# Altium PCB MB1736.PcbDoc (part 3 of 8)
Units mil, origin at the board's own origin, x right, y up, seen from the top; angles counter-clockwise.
Board outline 5905.51 x 3779.53 mil, 6 copper layers (Top Layer, L2_GND, L3_SIG, L4_VCC, L5_GND, Bottom Layer), stack 117.811 mil thick; 481 components, 387 nets, 1904 pads, 1200 vias.
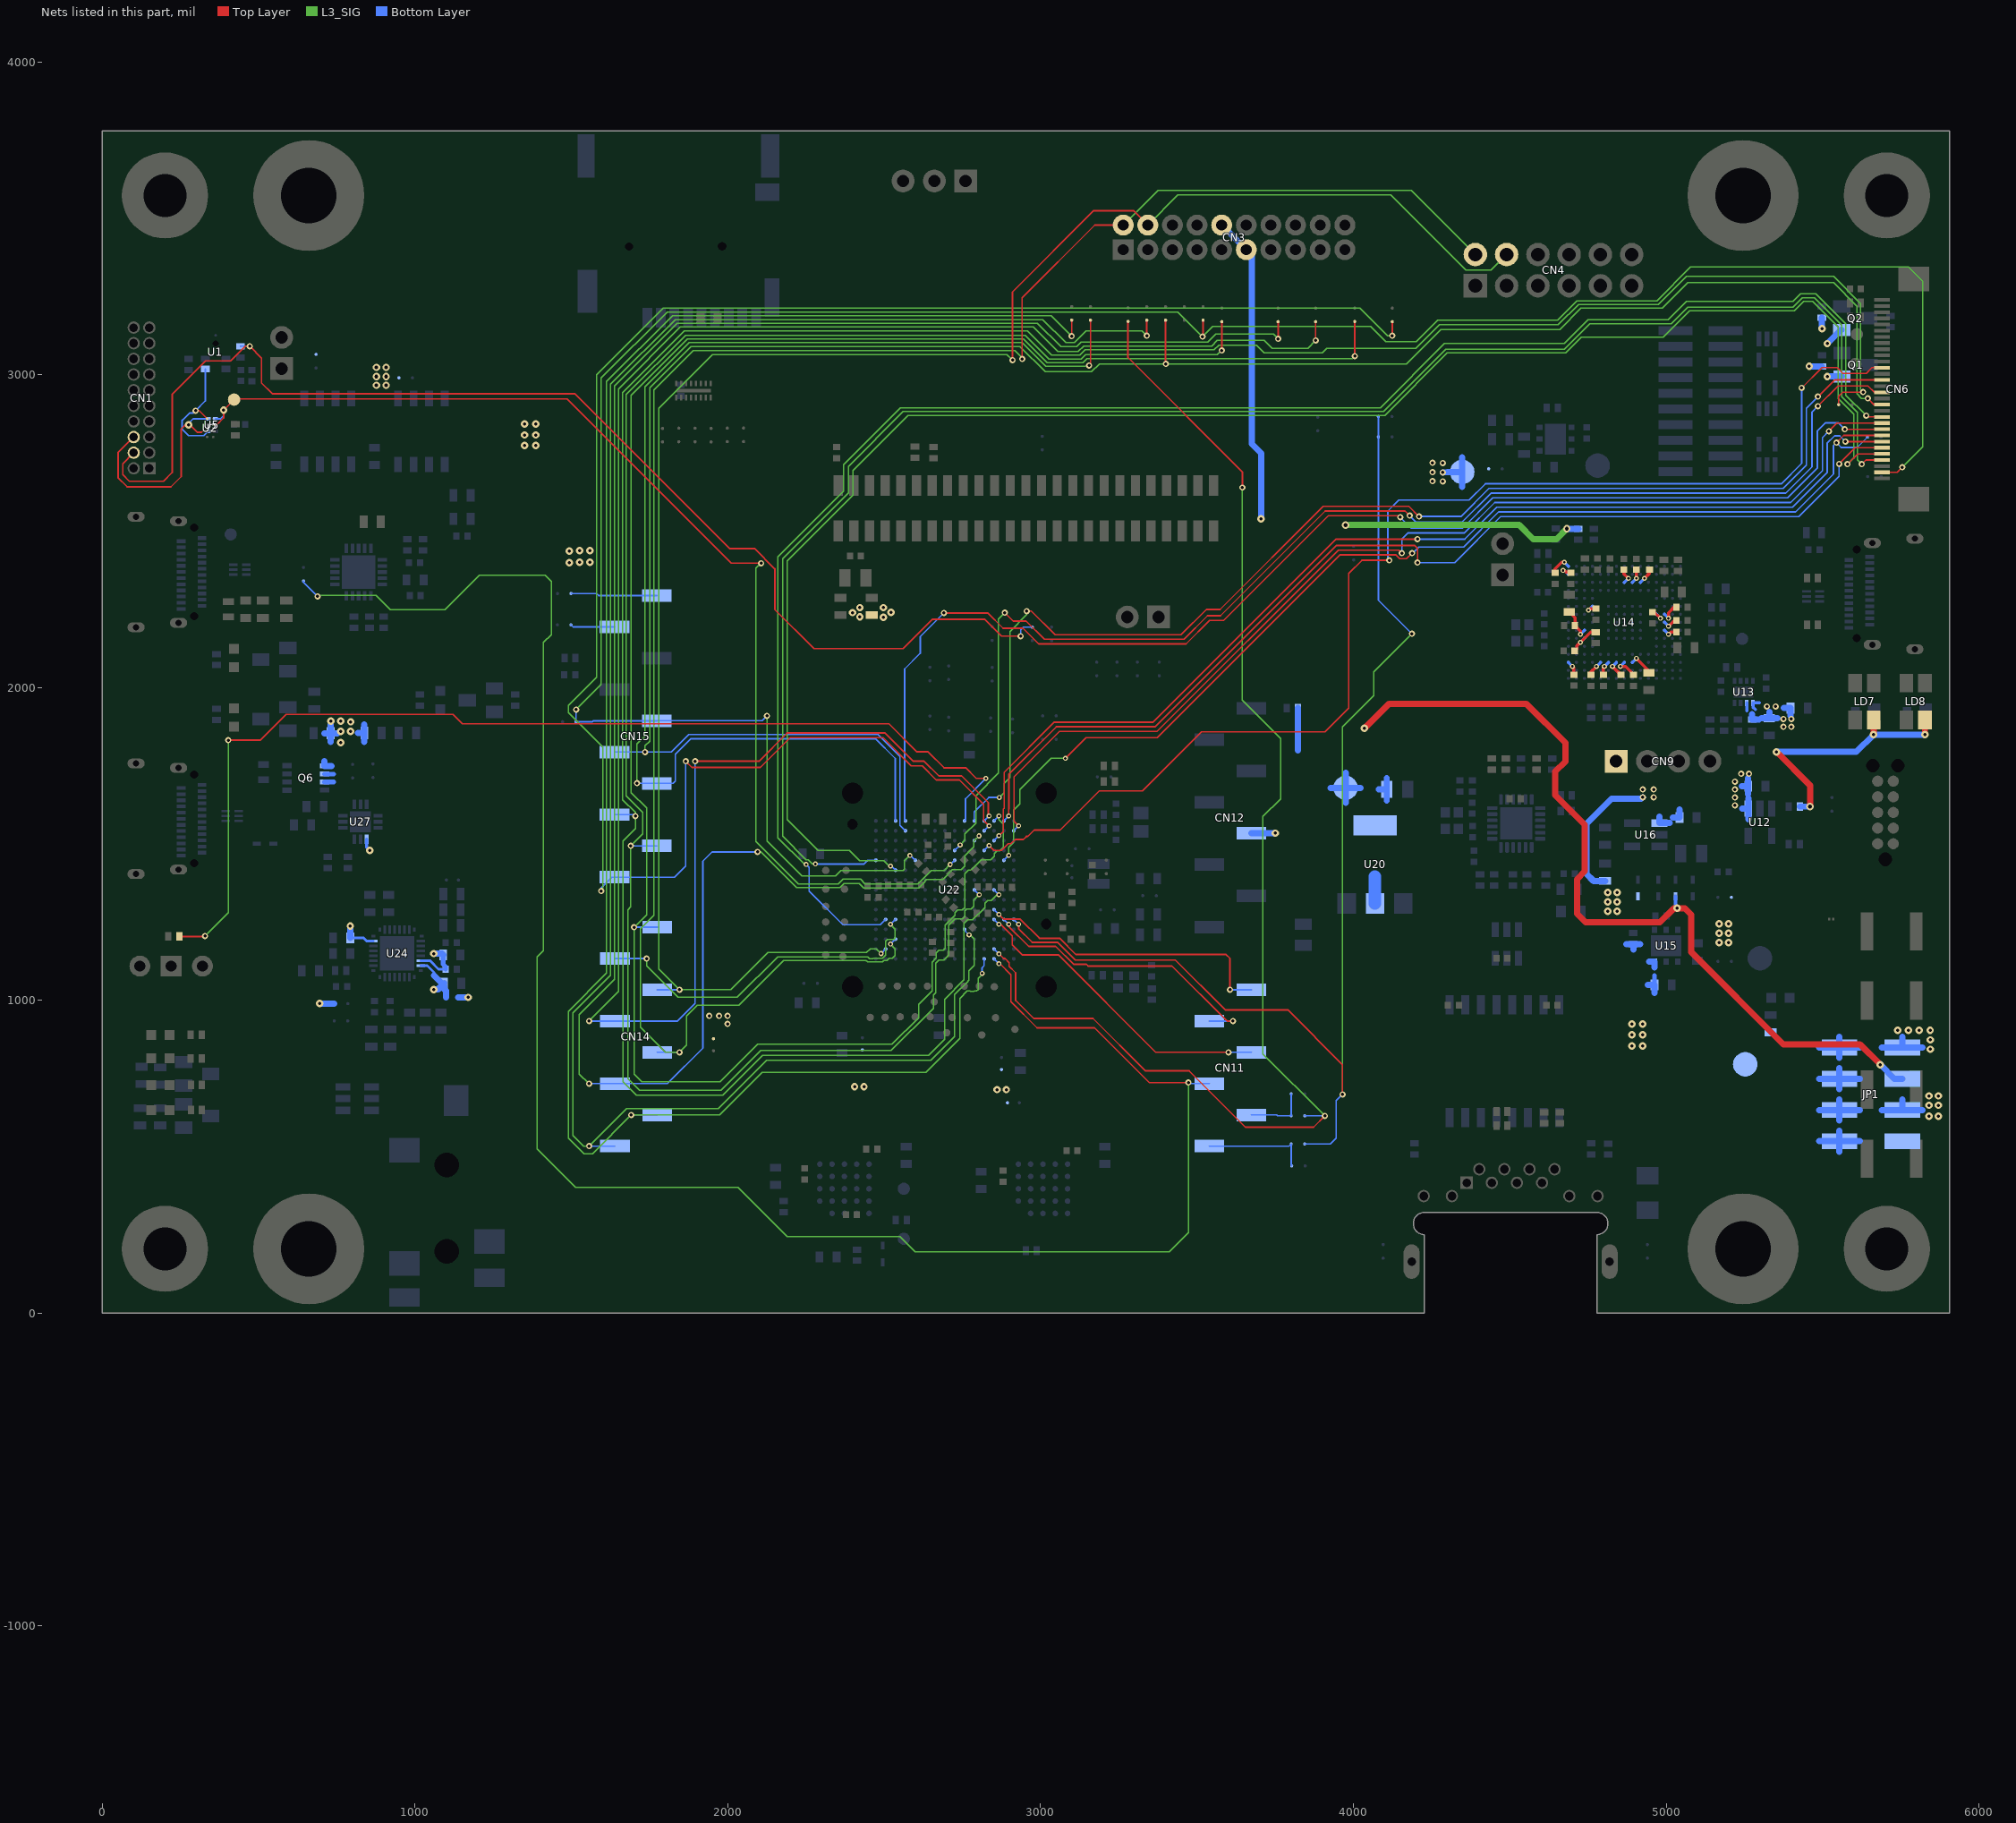
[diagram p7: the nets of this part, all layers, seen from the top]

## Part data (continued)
TP12 TP13 TP14 TP15 TP16 TP17 TP18 TP19 TP20 TP21 TP22 TP23 TP24 TP25 TP26 TP27 TP28 TP29 TP30 TP31 TP32 TP33 TP34 TP35 TP36 TP37 TP38 TP39 TP40 TP41 TP42: library part MCD-00631, "Test Point 0.6mm", Manufacturer=N/A
U1: library part MCD-02122, "MEMS sensors , omnidirectionnal digital microphone", Manufacturer=STMICROELECTRONICS, Manufacturer_HQ_COO=EU, Manufacturer_Part_Number=MP23DB01HPTR, Package="RHLGA 5"
U2: library part MCD-00668, "Low voltage 0.5 ohm single SPDT switch with break-before-make feature and 15 kV contact ESD protection", Manufacturer=STMICROELECTRONICS, Manufacturer_HQ_COO=EU, Manufacturer_Part_Number=STG4160BJR, Package="Flip Chip 8"
U3: library part MCD-00249, "ESD protection for SD card 2.0", Manufacturer=STMICROELECTRONICS, Manufacturer_HQ_COO=EU
U4 U10 U11: library part MCD-00136, "Dual Transil array for ESD protection", Manufacturer=STMICROELECTRONICS, Manufacturer_HQ_COO=EU
U5: library part MCD-02386, "Analog Switch, Low-ohmic single-pole double-throw analog switch", Manufacturer=NXP, Manufacturer_Part_Number=NX3L1T3157GMZ, Package=SOT886-6
U6 U7: library part MCD-03501, "Diode, ESD TVS, 5V5, 100nA, 10V, 0201", Manufacturer=STMICROELECTRONICS, Manufacturer_Part_Number=ESDZL5-1F4, Package=0201
U8 U29 U30: library part MCD-03060, "IC, ESD protection and Common Filter High Speed serial Interfaces, 10.7 GHz", Manufacturer=STMICROELECTRONICS, Package=uQFN-6
U9 U31 U32: library part MCD-01207, "High power Transient voltage suppressor:25V/35A EOS and ESD transients protection.", Manufacturer=STMICROELECTRONICS, Manufacturer_HQ_COO=EU, Manufacturer_Part_Number=ESDA25P35-1U1M, Package=QFN1610
U12: library part MCD-00159, "500mA, Enhanced single channel power switches with active high enable pin", Manufacturer=STMICROELECTRONICS, Manufacturer_HQ_COO=EU
U13: library part MCD-02532, "IC, eFuse with Fast Overvoltage Protection 2.7V to 18V 4A 34mOhm 8-Pin WSON", Manufacturer="TEXAS INSTRUMENTS", Package=WSON8
U14: library part MCD-02706, "MCU, Arm Cortex-M7 32-bit MCU, 512KB Flash, 276KB RAM, With Crypto", Manufacturer=STMICROELECTRONICS, Manufacturer_Part_Number=STM32F723IEK6, Package=BGA176
U15: library part MCD-01025, "LDO, 3.3V, 1.3A, Very low quiescent current BiCMOS voltage regulator", Manufacturer=STMICROELECTRONICS, Manufacturer_HQ_COO=EU, Package=DFN6-3x3
U16: library part MCD-02514, "LDO, 3.3V, 300mA, High input voltage: 2.5V to 28V, SOT23-5L", Manufacturer=STMICROELECTRONICS, Package=SOT23-5L
U17: library part MCD-00581, "LDO Linear Voltage Regulator IC Positive Adjustable 1 Output Adjustable 1.3A 6-DFN (3x3)", Manufacturer=STMICROELECTRONICS, Manufacturer_HQ_COO=EU, Package="DFN6 (3x3)"
U18: library part MCD-00719, "10/100M RMII Ethernet transceiver", Manufacturer=MICROCHIP
U19: library part MCD-00250, "Very low capacitance ESD protection , 4 lines", Manufacturer=STMICROELECTRONICS, Manufacturer_HQ_COO=EU
U20: library part MCD-00088, "IC REG LDO 5V 0.8A SOT223", Manufacturer=STMICROELECTRONICS, Manufacturer_HQ_COO=EU, Package=SOT-223
U21: library part MCD-02129, "Memory,Hexa-SPI-PSRAM,256Mb,x8x16,200MHz,1.8V,DDR,BGA24, PASR LVCMOS", Manufacturer="AP MEMORY TECHNOLOGY CORP.", Package=BGA24
U22: library part MCD-02603, "MCU, ARM Cortex M7 32-bit, 64KB Flash, 620KB RAM, No Crypto", Manufacturer=STMICROELECTRONICS, Package=TFBGA-225
U23: library part MCD-02601, "Memory, Octo-SPI-NOR, 1Gb,x1/x8, Read-While-Write, 133/200MHz, 1.8V, DTR, BGA24", Manufacturer=MACRONIX, Package=BGA24
U24: library part MCD-03825, "Audio Codec, Ultra Low-Power Codec for Portable Audio Applications", Manufacturer="CIRRUS LOGIC"
U26: library part MCD-02130, "USB Type-C Port Protection for USB DRP Power Delivery, PPS compliant", Manufacturer=STMICROELECTRONICS, Manufacturer_HQ_COO=EU, Package=QFN-20L
U27: library part MCD-01809, "USB Type-C Port Protection for USB Power Delivery, PPS compliant", Manufacturer=STMICROELECTRONICS, Manufacturer_HQ_COO=EU, Package=QFN-12L
U28: library part MCD-00247, "Quad Bidir ESD protection", Manufacturer=STMICROELECTRONICS, Manufacturer_HQ_COO=EU
U33: library part MCD-00718, "Discrete Magnetic Transformer Module, 16 pins, SMT, 100 Base-TX", Manufacturer="DONGGUAN KEYOUDA ELECTRONIC TECHNOLOGY"
X1: library part MCD-01036, "Crystal, 24MHz, 6pF, +/-20ppm, 80R, 2x1.6mm", Manufacturer=NDK, Manufacturer_Part_Number=NX2016SA-24MHZ-EXS00A-CS10820, Package=2x1.6mm
X2: library part MCD-01479, "Crystal, 32.768kHz, 6pF, +/-20ppm, 80K, 2.05x1.2mm", Manufacturer=NDK, Manufacturer_Part_Number=NX2012SA-32.768KHZ-EXS00A-MU00527, Package=2.05x1.2mm
X3: library part MCD-01627, "Oscillator, SPXO, 24MHz, +/-50ppm, square wave, 3V3, 2x1.6mm", Manufacturer=NDK, Manufacturer_Part_Number=NZ2016SH-24MHZ-END4869F, Package=2x1.6mm
X4: library part MCD-01364, "Crystal, 25MHz, 6pF, +/-20ppm, 80R, 2x1.6mm", Manufacturer=NDK, Manufacturer_Part_Number=NX2016SA-25MHZ-EXS00A-CS11321, Package=2x1.6mm

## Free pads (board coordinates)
  round 20 on Mech16: 1(1689.63,-1444.91) 1(3612.76,-1444.91)

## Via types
v1: diameter 20, hole 10, Top Layer to Bottom Layer, tented both sides, 518 vias
v2: diameter 16, hole 8, Top Layer to Bottom Layer, tented both sides, 311 vias
v3: diameter 24, hole 10, Top Layer to Bottom Layer, tented both sides, 301 vias
v4: diameter 24, hole 12, Top Layer to Bottom Layer, tented both sides, 61 vias
v5: diameter 23.62, hole 11.81, Top Layer to Bottom Layer, 9 vias

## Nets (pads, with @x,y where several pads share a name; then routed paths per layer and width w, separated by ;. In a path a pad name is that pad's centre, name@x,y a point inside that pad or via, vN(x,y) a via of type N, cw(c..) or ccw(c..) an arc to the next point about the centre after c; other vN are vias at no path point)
1V8: Q1.1 Q2.1 R64.2 R65.2 SB23.2 SB38.1 SB48.1 SB60.1 SB66.1 SB67.1 TP7.1 | length 376.8
  Bottom Layer w20: SB60.1@1137.72,1010 v3(1170.16,1010) ; v1(4285.9,2688.19) 4300.44,2689.77 TP7.1@4347.83,2689.77 ; 4347.83,2642.39 TP7.1@4347.83,2689.77 ; 4347.83,2737.17 TP7.1@4347.83,2689.77 ; v3(5457.72,3027.27) R64.2@5498,3027.3 ; v3(5497.95,3147.94) R65.2@5497.95,3183.48 ; v3(5515,2994.8) Q1.1@5562.19,2994.81 ; v3(5515,3100) 5558.79,3143.78 Q2.1@5561.37,3143.79
  other v1: 1999,925 1940,951 1972,951 1999,951 4252.9,2660.09 4285.9,2659.59 4252.9,2688.69 4252.9,2719.09 4285.9,2718.59
  other v3: 2860,715 2890,715 2405,725 2435,725
1V8_AUDIO: C127.2 C135.2 C139.2 C144.2 SB54.1 SB60.2 U24.6 U24.7 U24.23 | length 520.6
  Bottom Layer w8: C135.2@792.56,1200 835,1200 844.84,1190.16 U24.23@866.34,1190.16 ; U24.7@1017.91,1111.42 1038.58,1111.42 1060,1090 1060,1080 ; U24.6@1017.91,1127.17 1047.83,1127.17 1075,1100 C144.2@1097.28,1100
  Bottom Layer w15: C139.2@1089.57,1145.79 1089.57,1115.43 1097.28,1107.72 C144.2@1097.28,1100
  Bottom Layer w20: v3(695,990) 741.06,990 SB54.1@741.22,989.84 ; C135.2@792.56,1200 v3(792.56,1237.56) ; v3(1060,1035) 1072.44,1035 C127.2@1088.72,1051.28 ; 1060,1080 C127.2@1088.72,1051.28 ; v3(1060,1150) 1085.35,1150 C139.2@1089.57,1145.79 ; C127.2@1092.44,1055 C127.2@1088.72,1051.28 ; SB60.2@1099.33,1010 1099.33,1030.67 1092.44,1037.56 1092.44,1047.56 C127.2@1088.72,1051.28
3V3_STLK: C51.1 C52.1 C53.1 C54.2 C55.1 C56.1 C57.1 C58.1 C60.1 C62.1 C63.1 C64.1 C65.1 C66.2 C67.1 C68.1 C71.1 C72.1 C73.1 C87.2 CN9.1 LD7.4 LD8.4 R50.2 R68.1 R83.2 U14.C1 U14.C5 U14.C6 U14.C7 U14.C8 U14.C9 U14.F3 U14.G3 U14.G13 U14.H13 U14.J12 U14.J13 U14.K4 U14.N8 U14.N9 U14.N10 U14.P1 U14.R1 U16.1 | length 2494
  Top Layer w10: C51.1@4645,2367.72 4645,2379.99 4665.96,2400.94 v2(4674.68,2400.94) ; v2(4670,2375) 4675.04,2375 4681.11,2368.92 4693.79,2368.92 C55.1@4695,2367.72 ; C54.2@4689.94,2242.39 4708.68,2223.62 C53.1@4708.68,2198.4 ; v2(4700.27,2068.26) 4705.18,2063.35 C56.1@4705.18,2041.77 ; C52.1@4707.38,2117.65 4715,2125.27 4715,2134.17 v2(4725.86,2145.03) 4758.54,2177.72 R50.2@4775,2177.72 ; C53.1@4708.69,2198.39 4725.86,2181.22 v2(4725.86,2170.62) ; v2(4752.03,2247.98) 4756.39,2252.34 C58.1@4775.43,2252.34 ; C57.1@4759.53,2040.91 4759.53,2050.75 v2(4777.04,2068.26) ; C60.1@4799.53,2040.87 4799.53,2065.17 v2(4802.63,2068.26) ; v2(4828.22,2068.26) 4855.33,2041.16 C62.1@4855.33,2040.98 ; v2(4853.81,2068.26) 4870.4,2068.26 4895.33,2043.34 C64.1@4895.33,2041.02 ; C63.1@4865.1,2376.87 4865.1,2364.07 v2(4879.4,2349.76) ; v2(4904.99,2349.76) 4905.02,2363.11 C65.1@4905.02,2376.92 ; v2(4905.04,2093.85) 4945,2053.9 C66.2@4945,2047.55 ; v2(4930.58,2349.76) 4946.94,2366.12 C67.1@4946.94,2376.8 ; C68.1@4956.19,2241.11 4962.47,2241.09 v2(4981.76,2221.81) ; v2(5007.35,2170.62) 5014.95,2178.23 C72.1@5033.39,2178.23 ; v2(5007.35,2196.22) 5026.2,2215.07 C71.1@5033.14,2215.07 ; v2(5007.35,2221.81) 5007.35,2238.99 5025.7,2257.33 C73.1@5033.39,2257.33
  Top Layer w20: v3(5352.76,1795) 5460,1687.75 v4(5460,1620) ; v3(5663.53,1850) LD7.4@5663.54,1896.93 ; v3(5827.53,1850) LD8.4@5827.54,1896.93
  Bottom Layer w8: v2(4670,2375) 4675.04,2375 U14.P1@4687.5,2362.58
  Bottom Layer w10: v2(4674.68,2400.94) U14.R1@4687.47,2388.16 ; U14.C1@4687.48,2081.06 v2(4700.27,2068.26) ; v2(4725.86,2145.03) U14.F3@4738.68,2157.85 ; v2(4725.86,2170.62) U14.G3@4738.68,2183.44 ; v2(4752.03,2247.98) U14.K4@4764.27,2260.22 ; v2(4777.04,2068.26) U14.C5@4789.86,2081.08 ; v2(4802.63,2068.26) U14.C6@4815.45,2081.08 ; v2(4828.22,2068.26) U14.C7@4841.04,2081.08 ; v2(4853.81,2068.26) U14.C8@4866.64,2081.08 ; U14.N8@4866.64,2336.99 v2(4879.4,2349.76) ; U14.N9@4892.23,2336.99 v2(4904.99,2349.76) ; U14.C9@4892.23,2081.08 v2(4905.04,2093.85) ; U14.N10@4917.82,2336.99 v2(4930.58,2349.76) ; U14.J12@4969,2234.63 v2(4981.76,2221.81) ; U14.G13@4994.59,2183.44 v2(5007.35,2170.62) ; U14.H13@4994.59,2209.03 v2(5007.35,2196.22) ; U14.J13@4994.59,2234.63 v2(5007.35,2221.81)
  Bottom Layer w20: R83.2@4805,1382.45 4767.56,1382.43 4745,1405 4745,1565 4825,1645 4920,1645 v1(4925,1650) ; 4978.31,1587.24 U16.1@4978.32,1567.4 5011.92,1567.41 ; 5021.82,1585 C87.2@5042.44,1585 5042.44,1610.53 ; v3(5352.76,1795) 5608.53,1795 v3(5663.53,1850) v3(5827.53,1850) ; R68.1@5427.73,1620 v4(5460,1620)
  other v1: 4960,1650 4925,1675 4960,1675
5V: C88.2 CN3.6 CN3.15 CN12.5 JP1.2 JP1.4 JP1.6 JP1.8 R21.1 R69.1 R82.1 R88.2 SB64.1 TP5.1 U15.6 | length 2806.7
  L3_SIG w20: v4(3975,2520) 4530,2520 4575,2475 4649.15,2475 v4(4682.41,2508.25)
  Bottom Layer w15: C88.2@4962.44,1050 4962.44,1080.01 4962.6,1080.17
  Bottom Layer w20: CN3.15@3579,3479 CN3.6@3657.74,3400.25 3675,3383 3675,2780 3705,2750 v3(3705,2540) ; CN12.5@3674,1534.25 3749.26,1534.25 v3(3750,1535) ; v4(4682.41,2508.25) R88.2@4719.18,2508.25 ; 4873.2,1180.3 R82.1@4895,1180.31 ; 4895,1162.24 R82.1@4895,1180.31 ; 4916.8,1180.3 R82.1@4895,1180.31 ; 4941.82,1050 C88.2@4962.44,1050 4962.44,1024.45 ; 4945.73,1123.83 U15.6@4962.62,1123.83 4962.61,1105.97 ; 5489.13,550 JP1.8@5554.24,550 ; 5489.13,650 JP1.6@5554.24,650 ; 5489.13,750 JP1.4@5554.24,750 ; 5489.13,850 JP1.2@5554.24,850 ; 5554.24,516.39 JP1.8@5554.24,550 ; 5554.24,583.6 JP1.8@5554.24,550 ; 5554.24,616.39 JP1.6@5554.24,650 ; 5554.24,683.6 JP1.6@5554.24,650 ; 5554.24,716.39 JP1.4@5554.24,750 ; 5554.24,783.6 JP1.4@5554.24,750 ; 5554.24,816.39 JP1.2@5554.24,850 ; 5554.24,883.6 JP1.2@5554.24,850 ; 5619.35,550 JP1.8@5554.24,550 ; 5619.35,650 JP1.6@5554.24,650 ; 5619.35,750 JP1.4@5554.24,750 ; 5619.35,850 JP1.2@5554.24,850
  other v3: 4890,855 4925,855 4890,890 4925,890 4890,925 4925,925 2497,2225 2422,2226 2398,2240 2522,2241 2422,2256 2497,2256 1493,2400 1526,2401 1559,2401 1493,2437 1526,2438 1559,2438 1350,2774 1386,2774 1350,2808 1386,2808 1350,2843 1386,2843
5V_STLK: C4.1 C79.2 C80.2 JP1.1 R75.1 U12.1 U13.5 U13.6 | length 551
  Bottom Layer w10: 5257.89,1926.03 U13.6@5257.9,1951.23 ; 5285,1930 5277.57,1937.42 U13.5@5277.58,1951.23 5298.77,1951.23
  Bottom Layer w20: 5241.82,1685 C80.2@5262.44,1685 ; 5242.77,1613.3 U12.1@5262.6,1613.3 ; 5262.44,1659.45 C80.2@5262.44,1685 ; 5262.44,1710.53 C80.2@5262.44,1685 ; 5262.6,1579.68 U12.1@5262.6,1613.3 ; 5262.6,1646.91 U12.1@5262.6,1613.31 ; 5275,1915.78 R75.1@5275,1897.72 5296.8,1897.73 ; 5304.46,1902.56 C4.1@5330,1902.55 ; 5330,1923.17 C4.1@5330,1902.55 ; 5355.54,1902.56 C4.1@5330,1902.55 ; 5376.82,1935 C79.2@5397.44,1935 v1@5397.44,1909.45 ; 5689.91,850 JP1.1@5755.03,850 ; 5755.02,883.6 JP1.1@5755.03,850 ; 5820.13,850 JP1.1@5755.03,850
  other v1: 5220,1624 5220,1649 5220,1675 5220,1700 5240,1725 5265,1725 5375,1875 5400,1875 5375,1900 5400,1900 5322,1940 5350,1940
  other v3: 5845,844 5845,874 5740,905 5775,905 5809,905 5844,905
5V_UCPD: D6.1 JP1.7 SB61.1
  other v3: 4813,1285 4843,1285 4813,1315 4843,1315 4813,1345 4843,1345
  other v4: 876,2967 907,2967 876,2995 907,2995 876,3024 907,3024
5V_USB_SNK: JP1.5 Q6.1 Q6.2 Q6.3 R70.2 R158.1 SB22.2 U27.4 | length 474
  Bottom Layer w10: U27.4@844.68,1515.11 844.68,1490.32 v3(855,1480)
  Bottom Layer w15: Q6.3@710.04,1698.42 739.42,1698.42 ; Q6.2@710.04,1724.01 739.98,1724.01
  Bottom Layer w20: 709.43,1854.3 R158.1@730.05,1854.3 ; 710.04,1765.5 Q6.1@710.04,1749.6 732.83,1749.6 ; 730.05,1826.59 R158.1@730.05,1854.3 ; v3@730.05,1882 R158.1@730.05,1854.3 ; 750.67,1854.3 R158.1@730.05,1854.3 ; 816.82,1855 R70.2@837.44,1855 ; 837.44,1827.28 R70.2@837.44,1855 ; 837.44,1882.7 R70.2@837.44,1855 ; 5689.91,650 JP1.5@5755.03,650 ; 5755.02,683.6 JP1.5@5755.03,650 ; 5820.13,650 JP1.5@5755.03,650
  other v3: 5840,630 5870,630 5840,665 5870,665 5840,695 5870,695 5170,1185 5200,1185 5170,1215 5200,1215 5170,1245 5200,1245 762,1825 762,1860 793,1860 794,1891 730,1893 762,1893
5V_VIN: C103.2 D4.1 JP1.3 R108.2 TP8.1 U20.2 U20.4 | length 3250.6
  Top Layer w20: v3(4035,1870) 4114,1949 4552.21,1949 4677.5,1823.7 4677.5,1822.65 4677.75,1822.4 4677.75,1764.17 4645.5,1731.92 4645.5,1656.07 4740,1561.57 4740,1413 4715,1388 4715,1277 4742.01,1250 4980,1250 5025,1295 v3(5035,1295) 5060,1295 5080,1275 5080,1155 5375,860 5620,860 v3(5685,795)
  Bottom Layer w12: D4.1@5030,1333.42 5030,1300 v3(5035,1295)
  Bottom Layer w20: 3822.72,1800 R108.2@3822.74,1935 ; 3927.61,1680 TP8.1@3975,1680 ; 3975,1632.6 TP8.1@3975,1680 ; 3975,1727.39 TP8.1@3975,1680 ; 4022.39,1680 TP8.1@3975,1680 ; 4080.81,1675 C103.2@4106.55,1675 ; 4106.55,1639.42 C103.2@4106.55,1675 ; 4106.55,1710.58 C103.2@4106.55,1675 ; v3(5685,795) 5730,750 JP1.3@5755.03,750
  Bottom Layer w40: 4069,1396 4069.18,1395.82 U20.2@4069.2,1310.11
ARD_A0: CN11.1 U22.K3 | length 988
  Top Layer w5: v2(2866.61,1275) 2881.62,1260 2935,1260 2996,1199 3061,1199 3113,1147 3593,1147 3605,1135 3605,1035 v1(3605.75,1034.25)
  Bottom Layer w4: U22.K3@2850.89,1290.73 v2(2866.61,1275)
  Bottom Layer w5: v1(3605.75,1034.25) 3660,1034.25 CN11.1@3674,1034.25
ARD_A1: CN11.2 U22.L2 | length 947.2
  Top Layer w5: v2(2898.11,1243.5) 2898.11,1236.9 2962.01,1173 3048,1173 3105,1116 3146,1116 3152,1110 3420,1110 3595.75,934.25 v1(3615,934.25)
  Bottom Layer w4: U22.L2@2882.37,1259.25 v2(2898.11,1243.5)
  Bottom Layer w5: CN11.2@3539,934.25 v1(3615,934.25)
ARD_A2: CN11.3 U22.L3 | length 1016.2
  Top Layer w5: v2(2866.61,1243.5) 2872.5,1243.5 2909,1207 2909,1178 2941,1146 3056,1146 3367.76,834.25 v1(3600.75,834.25)
  Bottom Layer w4: U22.L3@2850.87,1259.25 v2(2866.61,1243.5)
  Bottom Layer w5: v1(3600.75,834.25) 3666,834.25 CN11.3@3674,834.25
ARD_A3: CN11.4 SB65.1 U22.R3 | length 6350.9
  Top Layer w5: v2(2866.61,1117.52) 2869.88,1117.52 2904.99,1082.42 2904.99,996.01 2988.51,912.5 3172.5,912.5 3347.5,737.5 v1(3472.5,737.5)
  L3_SIG w4: v1(687.76,2291.91) 690.85,2295 875,2295 920,2250 1095,2250 1205,2360 1415,2360 1435,2340 1435,2170 1410,2145 1410,1160 1390,1140 1390,525 1512.51,402.49 2032.5,402.49 2190,244.99 2550,244.99 2599,195.99 3411,195.99 3472.5,257.49 v1(3472.5,737.5)
  Bottom Layer w4: U22.R3@2850.9,1133.28 v2(2866.61,1117.52)
  Bottom Layer w5: SB65.1@642.76,2341.22 642.76,2336.91 v1(687.76,2291.91) ; v1(3472.5,737.5) 3475.75,734.25 3527,734.25 CN11.4@3539,734.25
ARD_A4: SB4.2 SB26.1 U22.P3 | length 4278.9
  Top Layer w5: v2(2866.61,1149.01) 2881.11,1134.51 2885.48,1134.51 2899.5,1120.5 2899.5,1109.12 2920,1088.62 2920,1021.58 2919.99,1000.01 2977.51,942.5 3167.5,942.5 3335,775 3475,775 3655,595 3872.56,595 v1(3908.78,631.22) ; SB4.2@3279.31,3171.12 3279.31,3055.68 3645,2690 v1(3645,2640)
  L3_SIG w4: v1(3645,2640) 3645,1960 3767,1838 3767,1644 3711,1588 3711,829 v1(3908.78,631.22)
  Bottom Layer w4: U22.P3@2850.87,1164.75 v2(2866.61,1149.01)
  Bottom Layer w5: SB26.1@3844.43,631.22 v1(3908.78,631.22)
ARD_A4_SDA: CN11.5 SB26.2 SB27.2 | length 198.3
  Bottom Layer w5: CN11.5@3674,634.25 3755,634.25 3758.04,631.22 SB26.2@3801.12,631.22 3801.11,693.89 ; 3801.11,694 SB27.2@3801.12,701.22
ARD_A5: SB25.1 SB50.2 SB74.2 U22.L1 | length 3907
  Top Layer w5: v2(2929.6,1243.5) 2929.6,1235.4 2929.64,1235.35 2929.64,1229.36 2973,1186 3054,1186 3110.69,1129.31 3430.69,1129.31 3590,970 3790,970 3965,795 v1(3965,700)
  L3_SIG w4: v1(3965,700) 3965,1875 4065,1975 4065,2050 v1(4187.38,2172.38)
  Bottom Layer w4: U22.L1@2913.86,1259.25 v2(2929.6,1243.5)
  Bottom Layer w5: SB25.1@3844.43,541.22 3926.22,541.22 3945,560 3945,680 v1(3965,700) ; SB50.2@4080,2867 SB74.2@4080,2802 4080,2279.75 v1(4187.38,2172.38)
ARD_A5_SCL: CN11.6 SB24.2 SB25.2 | length 335.7
  Bottom Layer w5: CN11.6@3539,534.25 3553.99,534.25 3794.13,534.25 3801.1,541.22 3801.1,472.8 SB24.2@3802.7,471.22
ARD_D0: CN14.1 SB5.1 U22.M6 | length 6199.5
  Top Layer w5: v1(3339.31,3125) SB5.1@3339.31,3175.06
  L3_SIG w4: v2(2771,1210) 2774.14,1210 2787,1197.14 2787,1112.6 2770,1095.6 2770,1065 2767,1062 2767,1061.03 2725,1019.03 2725,885 2649.01,809 2373.15,809 2372.88,809.27 2357.12,809.27 2356.85,809 2124.01,809 1970,655 1676.62,655 v1(1555.87,534.25) 1539,534.25 1505,568.25 1505,960 1625.18,1080.17 1625.18,2970.17 1832.01,3177 3007,3177 3081,3103 3108,3103 3145,3140 3324.31,3140 v1(3339.31,3125)
  Bottom Layer w5: v1(1555.87,534.25) CN14.1@1639,534.25 ; U22.M6@2756.4,1227.77 2756.4,1224.59 v2(2771,1210)
ARD_D1: CN14.2 SB1.1 U22.R4 | length 5934.3
  Top Layer w5: v1(3099.31,3124) SB1.1@3099.31,3175.06
  L3_SIG w4: v2(2812.88,1086.77) 2812.88,1084.07 2800,1071.18 2800,1035 2795,1030 2787.8,1030 2787.42,1029.61 2774.98,1029.61 2774.6,1030 2765,1030 2741.28,1006.27 2741.28,878.28 2633,770 2110,770 1974.25,634.25 v1(1690.87,634.25) 1566.62,510 1540,510 1490,560 1490,965 1612.18,1087.17 1612.18,2978.4 1822.78,3189 3034.31,3189 v1(3099.31,3124)
  Bottom Layer w5: v1(1690.87,634.25) CN14.2@1774,634.25 ; v2(2812.88,1086.77) 2812.88,1105.02 2819.39,1111.53 U22.R4@2819.4,1133.28
ARD_D2: CN14.3 SB12.2 U22.C5 | length 6687.7
  Top Layer w5: v1(3759.31,3115) SB12.2@3759.31,3170.06
  L3_SIG w4: v1(1555.87,734.25) 1525,765.11 1525,955 1637.18,1067.17 1637.18,2965.19 1836.99,3165 2990,3165 3065,3090 3115,3090 3130,3105 3535,3105 3560,3130 3744.31,3130 v1(3759.31,3115) ; v1(2095,1475) 2105,1475 2219,1361 2357.94,1361 2370.94,1374 2420,1374 2434,1360 2610.01,1360 2630,1380 2630,1382.98 2634,1386.98 2686.99,1386.98 2718.01,1418 2746,1418 2758.12,1430.11 2758.12,1463.11 2786.12,1491.11 2786.12,1509.45 v2(2802.83,1526.17)
  Bottom Layer w4: U22.C5@2787.9,1511.24 v2(2802.83,1526.17)
  Bottom Layer w5: v1(1555.87,734.25) CN14.3@1639,734.25 1806.26,734.25 1920,848 1920,1445 1950,1475 v1(2095,1475)
ARD_D3: CN3.11 CN4.7 CN14.4 U22.N13 | length 6348.4
  Top Layer w5: v1(2941,3051) 2941,3247 3173,3479 CN3.11@3264.04,3479
  L3_SIG w4: v2(2520.16,1180.5) 2535,1165.67 2535,1155 2534.57,1154.57 2534.57,1143.61 2526.37,1135.42 2515.42,1135.42 2508,1128 2499.2,1128 2494.2,1123 2447.01,1123 2442.01,1128 2178,1128 2035,985 1902,985 1868,951 1868,857.25 v1(1845,834.25) 1800,834.25 1720,914.25 1720,1229.43 1763,1272.43 1763,2952 1889,3078 2918,3078 2945,3051 v1(2941,3051) ; CN3.11@3264.04,3479 3375.04,3590 4185,3590 CN4.7@4390,3385
  Bottom Layer w5: CN14.4@1774,834.25 v1(1845,834.25) ; v2(2520.16,1180.5) U22.N13@2535.94,1196.27
ARD_D4: CN14.5 SB14.2 U22.A4 | length 6768.7
  Top Layer w5: v1(1895,1765) 2099,1765 2189,1855 2502.55,1855 2592.55,1765 2627.43,1765 2674.42,1718 2747,1718 2832.87,1632.13 2832.87,1592.18 v2(2835.11,1589.94) ; v1(3879.31,3110) SB14.2@3879.31,3170.06
  L3_SIG w4: v1(1555.87,934.25) 1650.18,1028.56 1650.18,2955.17 1848.01,3153 2977,3153 3055,3075 3120,3075 3137.5,3092.5 3547.5,3092.5 3565,3110 3715,3110 3740,3085 3854.31,3085 v1(3879.31,3110)
  Bottom Layer w4: U22.A4@2819.4,1574.23 v2(2835.11,1589.94)
  Bottom Layer w5: v1(1555.87,934.25) CN14.5@1639,934.25 1839.26,934.25 1895,990 v1(1895,1765)
ARD_D5: CN3.12 CN4.8 CN14.6 U22.P14 | length 5977.4
  Top Layer w5: v1(2910,3047) 2910,3265 3170,3525 3296.78,3525 CN3.12@3342.78,3479
  L3_SIG w4: v2(2489.65,1150) 2474.65,1165 2455,1165 2443,1153 2127.99,1153 2009.24,1034.25 v1(1845,1034.25) 1779,1100.25 1779,2893 1951,3065 2892,3065 v1(2910,3047) ; CN3.12@3342.78,3479 3438.78,3575 4120,3575 4360,3335 4440,3335 CN4.8@4490,3385
  Bottom Layer w4: v2(2489.65,1150) U22.P14@2504.44,1164.78
  Bottom Layer w5: CN14.6@1774,1034.25 v1(1845,1034.25)
ARD_D6: CN14.7 U22.L13 | length 1143.4
  L3_SIG w4: v1(1740,1134.25) 1740,1110 1840,1010 2030,1010 2160,1140 2446.41,1140 2452.31,1134.09 2463.91,1134.09 2464.81,1135 2494.81,1135 2505,1145.18 2505,1190 2510,1195 2530,1195 2535,1200 2535,1228.67 v2(2520.17,1243.5)
  Bottom Layer w5: CN14.7@1639.02,1134.25 1655.99,1134.25 v1(1740,1134.25) ; v2(2520.17,1243.5) U22.L13@2535.94,1259.27
ARD_D7: CN14.8 SB16.2 U22.A3 | length 6655.6
  Top Layer w5: v1(4004.31,3060) SB16.2@4004.31,3170.37
  L3_SIG w4: v2(2866.61,1589.94) 2866.61,1578.39 2880.62,1564.38 2880.62,1500.61 2880.61,1489.66 2868.92,1477.97 2860.81,1477.97 2852.61,1469.76 2852.61,1461.66 2840.92,1449.97 2809.98,1449.97 2778.48,1418.47 2778.3,1418.47 2776.83,1417 2768.34,1417 2757,1405.66 2757,1296.99 2749.02,1289 2734.83,1289 2726.63,1280.81 2726.63,1272.62 2723.01,1269 2722.7,1269 2702,1248.31 2702,1248 2695,1241 2695,1167.02 2688.29,1160.32 2674.53,1160.32 2666.33,1152.11 2666.33,1136.33 2652.5,1122.5 2652.5,1030 2623.26,1000.75 2623.17,1000.75 2614.39,991.98 2614.39,991.89 2610,987.5 2610,945 2525,860 2095,860 1974.99,739.99 1725.01,739.99 1700,765 v1(1700,1234.25) 1740,1274.25 1740,1615 1690,1665 1690,2935 1870,3115 2945,3115 3021.01,3038.99 3030.95,3038.99 3134.94,3039 3147.94,3052 3996.31,3052 v1(4004.31,3060)
  Bottom Layer w4: U22.A3@2850.9,1574.23 v2(2866.61,1589.94)
  Bottom Layer w5: v1(1700,1234.25) 1757,1234.25 CN14.8@1773.98,1234.25
ARD_D8: CN15.1 SB18.2 U22.B4 | length 6279.7
  Top Layer w5: v1(1865,1765) 1885,1745 2104,1745 2199,1840 2496.33,1840 2586.33,1750 2621.21,1750 2666.2,1705 2740,1705 2817.87,1627.13 2817.87,1575.69 v2(2835.11,1558.45) ; v1(4124.31,3125) SB18.2@4124.31,3170.06
  L3_SIG w4: v1(1595,1350) 1600,1355 1600,1810 1490,1920 1490,1944 1580,2034 1580,3000 1793.01,3213 4021.31,3213 4109.31,3125 v1(4124.31,3125)
  Bottom Layer w4: U22.B4@2819.4,1542.73 v2(2835.11,1558.45)
  Bottom Layer w5: v1(1595,1350) 1595,1360 1629.25,1394.25 CN15.1@1637.39,1394.25 1670.99,1394.25 1829.25,1394.25 1865,1430 v1(1865,1765)
ARD_D9: CN15.2 SB9.2 U22.H5 | length 6009.3
  Top Layer w5: v1(3579.31,3078) SB9.2@3579.31,3170.06
  L3_SIG w4: v2(2803.62,1338) 2786.32,1320.69 2786.32,1300.5 2778.12,1292.31 2763.64,1292.31 2758.12,1286.78 2758.12,1268.12 2751,1261 2726.02,1261 2710,1244.99 2710,1244.67 2706.5,1241.17 2706.5,1145.49 2690.01,1129 2685.96,1129 2685.88,1129.08 2674.28,1129.08 2664.5,1119.3 2664.5,1025.01 2657,1017.51 2657,975.01 2521.98,840 2105,840 1977.49,712.49 1717.51,712.49 1680.18,749.82 1680.18,1290.17 1689.25,1299.25 v1(1689.25,1494.25) 1728,1533 1728,1602 1675,1655 1675,2937 1865,3127 2949.98,3127 3025.98,3051 3129.96,3051 3143.96,3065 3564.31,3065 3577.31,3078 v1(3579.31,3078)
  Bottom Layer w4: U22.H5@2787.9,1353.76 v2(2803.62,1338)
  Bottom Layer w5: v1(1689.25,1494.25) 1762,1494.25 CN15.2@1772.39,1494.25
ARD_D10: CN15.3 SB19.2 U22.H3 | length 8631.4
  Top Layer w5: SB19.2@5551.69,2905 5551.69,2931.68 5565,2945 v1(5630,2945)
  L3_SIG w4: v2(2866.62,1337.99) 2859.98,1337.99 2841.4,1319.41 2829.8,1319.41 2821.6,1311.2 2821.6,1296.6 2782.5,1257.5 2766.32,1257.5 2755,1246.18 2755,1066.01 2692.5,1003.51 2692.5,876.5 2641,825 2111.22,825 1983.11,696.89 1708.11,696.89 1665.18,739.82 1665.18,1510.17 1704.25,1549.25 v1(1704.25,1589.25) 1704.25,1600.75 1663,1642 1663,2943 1860.01,3140 2957.5,3140 3034.5,3063 3124.98,3063 3141.98,3080 3555,3080 3570,3095 3690,3095 3715,3070 3900,3070 3915,3085 4200,3085 4275,3160 4655,3160 4720,3225 4975,3225 5065,3315 5535,3315 5622,3228 5622,2953 v1(5630,2945)
  Bottom Layer w5: CN15.3@1637.39,1594.25 1660.99,1594.25 1699.25,1594.25 v1(1704.25,1589.25) ; U22.H3@2850.9,1353.76 v2(2866.62,1337.99)
ARD_D11: CN15.4 SB2.1 U22.A13 | length 4104.1
  Top Layer w5: v1(3155,3030) 3159.31,3034.31 SB2.1@3159.31,3175.06
  L3_SIG w4: v1(1709.63,1694.61) 1709.63,1819.62 1735,1845 1735,2962 1876,3103 2940.01,3103 3016.03,3026.99 3035.93,3026.99 ; 3035.94,3027 3152,3027 v1(3155,3030)
  Bottom Layer w5: v1(1709.63,1694.61) 1710,1694.25 CN15.4@1780,1694.25 ; CN15.4@1772.39,1694.25 CN15.4@1779.99,1694.25 ; U22.A13@2535.94,1574.23 2535,1575.16 2535,1773.77 2471.77,1837 1882,1837 1832,1787 1832,1702 1824.26,1694.25 CN15.4@1779.99,1694.25
ARD_D12: CN6.13 CN15.5 SB6.1 U22.B12 | length 6992.4
  Top Layer w5: SB6.1@3399.31,3175.06 3399.31,3035.68 v1(3400,3035) ; v1(5645,2925) 5664.96,2905.03 CN6.13@5690,2905.03
  L3_SIG w4: v1(1735,1794.25) 1735,1814.25 1750,1829.25 1750,2959 1882,3091 2934,3091 3015,3010 3163,3010 3188,3035 v1(3400,3035) 4170,3035 4280,3145 4660,3145 4728,3213 4988,3213 5070,3295 5535,3295 5610,3220 5610,2940 5625,2925 v1(5645,2925)
  Bottom Layer w5: CN15.5@1637.39,1794.25 1644.99,1794.25 v1(1735,1794.25) 1819.25,1794.25 1875.01,1850 2480,1850 2550,1780 2550,1560.12 2558.56,1551.57 U22.B12@2567.43,1542.73
ARD_D13: CN6.2 CN15.6 SB8.1 SB56.1 U22.E11 | length 7963.1
  Top Layer w5: v1(3517.5,3122.5) 3519.31,3124.31 SB8.1@3519.31,3175.06 ; CN6.2@5690,2688.5 5738.51,2688.5 v1(5755,2705)
  L3_SIG w4: v1(1514.4,1930) 1595,2010.59 1595,2990 1806.01,3201 3439,3201 v1(3517.5,3122.5) 3550,3155 4055,3155 4103.69,3106.31 4201.31,3106.31 4270,3175 4653.02,3175 4715.02,3237 4970.02,3237 5078.02,3345 5775,3345 5820,3300 5820,2770 v1(5755,2705) ; v1(2125,1910) 2125,1510 2237,1398 2344,1398 2361,1415 2559.99,1415 2565,1420 2565,1446.58 v2(2582,1463.58)
  Bottom Layer w4: v2(2582,1463.58) 2583.55,1463.58 2592.56,1454.57 U22.E11@2598.93,1448.24
  Bottom Layer w5: v1(1514.4,1930) 1514.4,1891.22 1567,1891.22 1570.04,1894.25 CN15.6@1772.39,1894.25 1773.13,1895 2110,1895 v1(2125,1910)
ARD_D14: CN15.9 SB59.2 | length 142.3
  Bottom Layer w5: SB59.2@1498.06,2201.22 1505,2194.25 CN15.9@1637.4,2194.25
ARD_D15: CN15.10 SB58.2 | length 276.9
  Bottom Layer w5: SB58.2@1498.37,2301.22 1580,2301.22 1586.97,2294.25 CN15.10@1772.37,2294.25
BOOT0: R1.2 U22.A6 | length 3445.7
  Top Layer w5: R1.2@245.62,1204.68 326.54,1204.68 v1(327.76,1205.91) ; v1(402.76,1832.19) 504.2,1832.19 587,1915 1121,1915 1151,1885 2514.99,1885 2604.99,1795 2639.87,1795 2690.86,1744 2760,1744 2794.01,1710 v2(2825,1710)
  L3_SIG w4: v1(327.76,1205.91) 402.76,1280.91 v1(402.76,1832.19)
  Bottom Layer w5: U22.A6@2756.38,1574.2 2760,1577.83 2760,1645 v2(2825,1710)
CK: CN1.4 R2.2 SB49.1 | length 3964
  Top Layer w5: CN1.4@100,2751.22 65,2716.22 65,2681 86,2660 195,2660 223,2688 223,2938 330,3045 410,3045 456.72,3091.72 v1(471,3091.72) 509,3053.72 509,2974 543,2940 1510,2940 2005,2445 2085,2445 2150,2380 2150,2250 2275,2125 2560,2125 2654,2219 2821,2219 2875,2165 v1(2936,2165)
  Bottom Layer w5: R2.2@441.93,3091.55 442.09,3091.72 v1(471,3091.72) ; v1(2936,2165) 2936,2185 2944.68,2193.68 SB49.1@2973,2193.68
D1: TP11.1 U2.7 U5.4 U22.E7 | length 3697
  Top Layer w5: U2.7@354.45,2840.71 365.68,2840.68 387.78,2862.78 v3(387.78,2887.78) TP11.1@421,2921 423.22,2923.22 1485.78,2923.22 2011,2398 v1(2106,2398)
  L3_SIG w4: v1(2106,2398) 2090,2382 2090,1508.01 2225.02,1373 2352.96,1373 2367.96,1388 2423.96,1388 2438.96,1373 2608.01,1373 2650,1415 2691.07,1415 v2(2710.83,1434.75)
  Bottom Layer w4: v2(2710.83,1434.75) 2711.42,1434.75 U22.E7@2724.91,1448.24
  Bottom Layer w5: U5.4@361.81,2859.69 377.47,2859.69 387.78,2870 v3(387.78,2887.78)
Data_Con: CN1.6 U2.3 U5.3 | length 704.2
  Top Layer w5: CN1.6@100,2801.22 50,2751.22 50,2671 79,2642 219,2642 252,2675 252,2827 265,2840 v3(275,2840) 280,2840 303,2817 317,2817 321.02,2821.02 U2.3@334.76,2821.02
  Bottom Layer w5: v3(275,2840) 275,2845 289.69,2859.69 U5.3@338.19,2859.69
Data_Mems: U1.1 U2.1 U5.1 | length 375.5
  Top Layer w5: v1(298,2886) 309.16,2886 U2.1@334.76,2860.39
  Bottom Layer w5: U1.1@329,3019.07 329,2917 v1(298,2886) 290,2878 278,2878 255,2855 255,2826 275,2806 323.87,2806 U5.1@338.19,2820.32
DCMI_D0: CN6.4 U22.E15 | length 5586.6
  Top Layer w5: v1(5625.42,2714.59) 5638.71,2727.88 CN6.4@5690,2727.88
  L3_SIG w4: v2(2280,1436.5) 2269.72,1436.5 2256.22,1450 2250,1450 2175,1525 2175,2412.42 2385,2622.42 2385,2707.42 2560.57,2883 4096.02,2883 4295.02,3082 4673.82,3082 4755.82,3164 5017.02,3164 5070.03,3217 5079.97,3217 5405.02,3217 5435.02,3247 5474.03,3247 5562,3159.02 5562,2929.98 5612,2879.98 5612,2728 v1(5625.42,2714.59)
  Bottom Layer w5: v2(2280,1436.5) 2435.5,1436.5 2447.23,1448.23 U22.E15@2472.94,1448.24
DCMI_D1: CN6.5 U22.F13 | length 5615.4
  Top Layer w5: v1(5580,2715) 5612.56,2747.56 CN6.5@5690,2747.56
  L3_SIG w4: v2(2520,1429.97) 2517.5,1432.47 2512.54,1432.47 2498.01,1447 2422,1447 2389,1480 2288.01,1480 2190,1578.01 2190,2405 2400,2615 2400,2695 2576,2871 4101,2871 4300,3070 4678.8,3070 4728.8,3120 4990,3120 5075,3205 5410,3205 5440,3235 5469.05,3235 5550,3154.05 5550,2924.99 5600,2874.99 5600,2735 v1(5580,2715)
  Bottom Layer w4: v2(2520,1429.97) 2522.67,1429.97 U22.F13@2535.94,1416.75
DCMI_D2: CN6.6 U22.A2 | length 3475.1
  Top Layer w4: v2(2898.11,1589.94) 2898.11,1612.12
  Top Layer w5: 2898.11,1612.12 2898.11,1723.1 3050,1875 3366,1875 3946,2455 4195,2455 4205,2445 v1(4205,2400) ; v1(5552.9,2715.4) 5604.75,2767.25 CN6.6@5690,2767.25
  Bottom Layer w4: U22.A2@2882.39,1574.23 v2(2898.11,1589.94)
  Bottom Layer w5: v1(4205,2400) 4323.78,2400 4470.68,2546.9 5424.22,2546.9 5552.9,2675.58 v1(5552.9,2715.4)
DCMI_D3: CN6.7 U22.C3 | length 3546.5
  Top Layer w4: v2(2866.62,1526.97) 2880,1540.34 2880,1552.05 2880.62,1552.67 2880.62,1564.26 2880.61,1612.12
  Top Layer w5: 2880.61,1612.12 2883.11,1614.62 2883.11,1729.33 3043.78,1890 3360,1890 3945,2475 v1(4205,2475) ; v1(5573.07,2786.92) CN6.7@5690,2786.92
  Bottom Layer w4: U22.C3@2850.9,1511.24 v2(2866.62,1526.97)
  Bottom Layer w5: v1(4205,2475) 4356.34,2475 4458.24,2576.9 5404.22,2576.9 5514.7,2687.38 5514.7,2781.3 5538.5,2805.09 5554.9,2805.09 v1(5573.07,2786.92)
DCMI_D4: CN6.8 SB75.2 U22.E2 | length 3655.8
  Top Layer w5: v2(3079,1774) 3145,1840 3373,1840 3958,2425 4135.25,2425 4147.75,2412.5 4170,2412.5 v1(4187.5,2430) ; v1(5544.3,2783.19) 5567.72,2806.61 CN6.8@5690,2806.61
  L3_SIG w4: v2(2898.11,1463.97) 2898.11,1490.1 2914,1506 2914,1608 2934,1628 2934,1675.02 3032.98,1774 v2(3079,1774)
  Bottom Layer w4: U22.E2@2882.39,1448.24 v2(2898.11,1463.97)
  Bottom Layer w5: v1(4187.5,2430) 4190,2430 4210,2450 4352.56,2450 4464.46,2561.9 5413.76,2561.9 5535.1,2683.24 5535.1,2774 v1(5544.3,2783.19) 5559.5,2768 5610.69,2768 SB75.2@5643.69,2801
DCMI_D5: CN6.9 U22.A12 | length 4161.6
  Top Layer w5: v1(2691,2239) 2831,2239 2880,2190 2943.22,2190 2993.22,2140 3465.01,2140 3540,2215 3585.02,2215 3920.02,2550 4145,2550 v1(4150,2545) ; v1(5571.3,2826.3) CN6.9@5690,2826.3
  Bottom Layer w5: U22.A12@2567.43,1574.23 2565,1576.66 2565,2060 2615,2110 2615,2163 v1(2691,2239) ; v1(4150,2545) 4185,2510 4348.9,2510 4445.8,2606.9 5388,2606.9 5483.8,2702.69 5483.8,2821.4 5508.8,2846.4 5551.2,2846.4 v1(5571.3,2826.3)
DCMI_D6: CN6.10 U22.B1 | length 3525.1
  Top Layer w4: 2915,1612.12 2915,1573.06 v2(2929.6,1558.45)
  Top Layer w5: 2915,1612.12 2915,1715 3060,1860 3372,1860 3952,2440 4145,2440 v1(4155,2430) ; v1(5520,2820) 5545.99,2845.99 CN6.10@5690,2845.99
  Bottom Layer w4: U22.B1@2913.89,1542.73 v2(2929.6,1558.45)
  Bottom Layer w5: v1(4155,2430) 4155,2475 4175,2495 4355.12,2495 4452.02,2591.9 5398,2591.9 5499.6,2693.5 5499.6,2799.59 v1(5520,2820)
DCMI_D7: CN6.11 U22.L14 | length 5633.6
  Top Layer w5: v1(5640,2870) 5644.33,2865.67 CN6.11@5690,2865.67
  L3_SIG w4: v2(2250,1435) 2245,1435 2160,1520 2160,2418.66 2370,2628.66 2370,2713.65 2551.35,2895 4085.96,2895 4290.96,3100 4674.84,3100 4750.84,3176 5006,3176 5065,3235 5406.04,3235 5430.04,3259 5479.01,3259 5575,3163.01 5575,2935 v1(5640,2870)
  Bottom Layer w5: v2(2250,1435) 2260,1425 2260,1349.99 2367.86,1242.12 2487.29,1242.12 U22.L14@2504.44,1259.27
DCMI_HSYNC: CN6.17 U22.A5 | length 3997.8
  Top Layer w5: v1(2955,2245) 2970,2245 3046,2169 3449.01,2169 3530,2250 3573.79,2250 3903.79,2580 4177.5,2580 v1(4210,2547.5) ; v1(5485.5,2930.5) 5538.78,2983.77 CN6.17@5690,2983.77
  L3_SIG w4: v2(2867.59,1649) 2868.22,1649 2884,1664.77 2884,1694.93 2902,1712.93 2902,2180 2955,2233 v1(2955,2245)
  Bottom Layer w5: U22.A5@2787.9,1574.23 2787.88,1602.88 2834,1649 v2(2867.59,1649) ; v1(4210,2547.5) 4343.96,2547.5 4433.42,2636.95 4661.75,2636.95 4736.24,2636.9 5374.22,2636.9 5448.6,2711.27 5448.6,2893.59 v1(5485.5,2930.5)
DCMI_PIXCLK: CN6.15 U22.D7 | length 4142.3
  Top Layer w5: v1(2885,2240) 2912,2213 2953.68,2213 3011.68,2155 3458.78,2155 3533.78,2230 3575.01,2230 3910.01,2565 4165,2565 v1(4180,2550) ; v1(5485,2900) 5550,2965 5645,2965 5665.59,2944.41 CN6.15@5690,2944.41
  L3_SIG w4: v2(2742.59,1497.42) 2758.12,1512.94 2758.12,1532.75 2793,1567.64 2793,1654.88 2865,1726.88 2865,2220 v1(2885,2240)
  Bottom Layer w4: U22.D7@2724.89,1479.72 v2(2742.59,1497.42)
  Bottom Layer w5: v1(4180,2550) 4200,2530 4347.68,2530 4439.58,2621.9 5381.78,2621.9 5466.5,2706.61 5466.5,2881.5 v1(5485,2900)
DCMI_VSYNC: CN6.19 U22.D4 | length 4030.3
  Top Layer w5: v2(2835.11,1495.45) 2850.57,1480 2875,1480 2896,1501 2905.39,1501 2919.39,1515 2945,1515 2954.53,1524.52 2958.62,1524.52 2979.09,1545 3062.44,1545 3187.44,1670 3325,1670 3514,1859 3909,1859 3985,1935 3985,2365 4027.5,2407.5 v1(4115,2407.5) ; v1(5433.3,2958.3) 5498.15,3023.15 5546.84,3023.15 5564.99,3005 5640.01,3005 5658.16,3023.15 CN6.19@5690,3023.15
  Bottom Layer w4: U22.D4@2819.4,1479.74 v2(2835.11,1495.45)
  Bottom Layer w5: v1(4115,2407.5) 4115,2410 4110,2415 4110,2565 4145,2600 4370,2600 4421.96,2651.95 4661.76,2651.95 4736.25,2651.9 5368,2651.9 5433.3,2717.19 v1(5433.3,2958.3)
